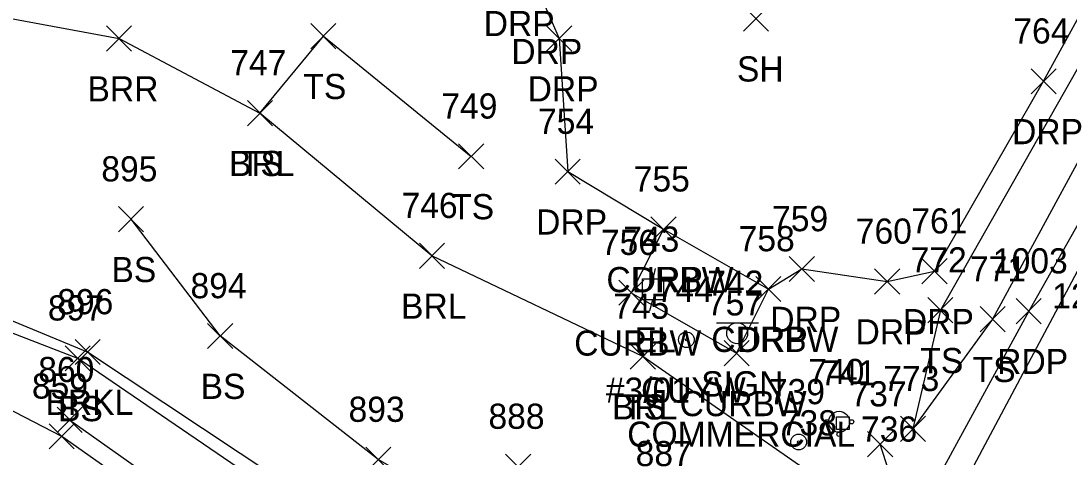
# Model space of a CAD drawing. Extents: x 1639430 to 1640195, y 612006 to 612917.
# Drawn here: x 1639766.2 to 1639849.6, y 612632.9 to 612667.5 of the extents above; entities that cross this region are included whole.
import ezdxf

# ---------------------------------------------------------------- set-up
doc = ezdxf.new("R2010")
doc.units = 0
for name, color, linetype in [('C_I', 7, 'Continuous'), ('CPBM', 7, 'Continuous'), ('D_I', 7, 'Continuous'), ('L_A', 7, 'Continuous'), ('L_I', 7, 'Continuous'), ('L_TIC', 7, 'Continuous'), ('LABL', 7, 'Continuous'), ('LAWE', 7, 'Continuous'), ('LELB', 7, 'Continuous'), ('M_I', 7, 'Continuous'), ('MPIR', 7, 'Continuous'), ('P_A', 7, 'Continuous'), ('P_I', 7, 'Continuous'), ('P_TIC', 7, 'Continuous'), ('PET', 7, 'Continuous'), ('R_A', 7, 'Continuous'), ('R_I', 7, 'Continuous'), ('R_TIC', 7, 'Continuous'), ('RC', 7, 'Continuous'), ('RDP', 7, 'Continuous'), ('RGR', 7, 'Continuous'), ('S_A', 7, 'Continuous'), ('S_C', 7, 'Continuous'), ('S_I', 7, 'Continuous'), ('SSGN', 7, 'Continuous'), ('U_A', 7, 'Continuous'), ('U_C', 7, 'Continuous'), ('U_I', 7, 'Continuous'), ('UEPT', 7, 'Continuous'), ('UPGW', 7, 'Continuous'), ('UW', 7, 'Continuous'), ('UWFH', 7, 'Continuous')]:
    doc.layers.add(name, color=color, linetype=linetype)

msp = doc.modelspace()

# ---------------------------------------------------------------- linework, layer by layer
at = {"layer": 'CPBM'}
for p, q in [((1639831.084, 612635.092), (1639831.084, 612636.092)), ((1639831.084, 612636.092), (1639832.084, 612636.092)), ((1639831.587, 612635.592), (1639831.587, 612635.592)), ((1639831.587, 612635.592), (1639831.587, 612635.592)), ((1639832.084, 612636.092), (1639832.084, 612635.092)), ((1639832.084, 612635.092), (1639831.084, 612635.092))]:
    msp.add_line(p, q, dxfattribs=at)
at = {"layer": 'L_TIC'}
for points in [[(1639823.679, 612666.738), (1639825.679, 612668.738)], [(1639825.679, 612666.738), (1639823.679, 612668.738)], [(1639773.027, 612665.155), (1639775.027, 612667.155)], [(1639775.027, 612665.155), (1639773.027, 612667.155)], [(1639789.272, 612665.346), (1639791.272, 612667.346)], [(1639791.272, 612665.346), (1639789.272, 612667.346)], [(1639784.228, 612659.23), (1639786.228, 612661.23)], [(1639786.228, 612659.23), (1639784.228, 612661.23)], [(1639784.228, 612659.23), (1639786.228, 612661.23)], [(1639786.228, 612659.23), (1639784.228, 612661.23)], [(1639801.028, 612655.794), (1639803.028, 612657.794)], [(1639803.028, 612655.794), (1639801.028, 612657.794)], [(1639773.976, 612650.801), (1639775.976, 612652.801)], [(1639775.976, 612650.801), (1639773.976, 612652.801)], [(1639797.909, 612647.895), (1639799.909, 612649.895)], [(1639799.909, 612647.895), (1639797.909, 612649.895)], [(1639838.342, 612643.566), (1639840.342, 612645.566)], [(1639840.342, 612643.566), (1639838.342, 612645.566)], [(1639842.497, 612642.862), (1639844.497, 612644.862)], [(1639844.497, 612642.862), (1639842.497, 612644.862)], [(1639781.07, 612641.52), (1639783.07, 612643.52)], [(1639783.07, 612641.52), (1639781.07, 612643.52)], [(1639770.525, 612640.248), (1639772.525, 612642.248)], [(1639772.525, 612640.248), (1639770.525, 612642.248)], [(1639769.728, 612639.749), (1639771.728, 612641.749)], [(1639771.728, 612639.749), (1639769.728, 612641.749)], [(1639814.683, 612639.888), (1639816.683, 612641.888)], [(1639816.683, 612639.888), (1639814.683, 612641.888)], [(1639814.683, 612639.888), (1639816.683, 612641.888)], [(1639816.683, 612639.888), (1639814.683, 612641.888)], [(1639769.094, 612634.855), (1639771.094, 612636.855)], [(1639771.094, 612634.855), (1639769.094, 612636.855)], [(1639768.465, 612633.546), (1639770.465, 612635.546)], [(1639770.465, 612633.546), (1639768.465, 612635.546)], [(1639836.164, 612634.143), (1639838.164, 612636.143)], [(1639838.164, 612634.143), (1639836.164, 612636.143)], [(1639836.164, 612634.143), (1639838.164, 612636.143)], [(1639838.164, 612634.143), (1639836.164, 612636.143)], [(1639793.64, 612631.699), (1639795.64, 612633.699)], [(1639795.64, 612631.699), (1639793.64, 612633.699)], [(1639804.765, 612631.144), (1639806.765, 612633.144)], [(1639806.765, 612631.144), (1639804.765, 612633.144)]]:
    msp.add_lwpolyline(points, dxfattribs=at)
at = {"layer": 'LABL'}
for points in [[(1639710.204, 612699.828), (1639711.051, 612687.806), (1639724.433, 612679.592), (1639743.791, 612671.782), (1639774.027, 612666.155)], [(1639774.027, 612666.155), (1639785.228, 612660.23)], [(1639815.683, 612640.888), (1639798.909, 612648.895), (1639785.228, 612660.23)]]:
    msp.add_lwpolyline(points, dxfattribs=at)
at = {"layer": 'LAWE'}
for points in [[(1639771.525, 612641.248), (1639744.188, 612652.549)], [(1639818.397, 612622.252), (1639806.958, 612625.66), (1639792.808, 612627.122), (1639771.525, 612641.248)], [(1639769.465, 612634.546), (1639758.328, 612640.278)], [(1639815.502, 612605.955), (1639811.555, 612610.222), (1639810.816, 612611.799), (1639809.099, 612612.433), (1639807.886, 612612.157), (1639806.874, 612611.255), (1639802.154, 612613.218), (1639796.025, 612614.881), (1639785.071, 612623.534), (1639769.465, 612634.546)]]:
    msp.add_lwpolyline(points, dxfattribs=at)
at = {"layer": 'LELB'}
for points in [[(1639856.893, 612675.516), (1639839.342, 612644.566), (1639837.164, 612635.143)], [(1639856.893, 612675.516), (1639858.232, 612671.011), (1639843.497, 612643.862), (1639837.164, 612635.143)], [(1639785.228, 612660.23), (1639790.272, 612666.346), (1639802.028, 612656.794)], [(1639806.958, 612625.66), (1639794.64, 612632.699), (1639782.07, 612642.52), (1639774.976, 612651.801)], [(1639745.954, 612650.314), (1639770.728, 612640.749)], [(1639764.188, 612527.424), (1639772.977, 612544.039), (1639792.096, 612560.955), (1639798.045, 612571.861), (1639798.637, 612584.242), (1639801.408, 612590.442), (1639806.01, 612591.217), (1639813.347, 612604.755), (1639814.159, 612604.989), (1639815.502, 612605.955), (1639817.508, 612607.626), (1639823.926, 612612.002), (1639825.414, 612614.447), (1639825.954, 612618.423), (1639826.214, 612622.256), (1639826.372, 612626.105), (1639824.294, 612621.683), (1639822.313, 612620.482), (1639821.077, 612619.388), (1639821.02, 612619.326), (1639817.573, 612621.321), (1639806.603, 612624.212), (1639792.365, 612626.015), (1639770.728, 612640.749)], [(1639770.341, 612524.498), (1639771.372, 612528.696), (1639778.638, 612537.492), (1639795.972, 612561.5), (1639808.106, 612583.963), (1639817.63, 612601.539), (1639820.453, 612607.731), (1639824.84, 612610.698), (1639833.386, 612626.603), (1639829.018, 612631.624), (1639815.683, 612640.888)], [(1639770.094, 612635.855), (1639784.877, 612625.393), (1639800.41, 612616.513), (1639807.846, 612612.518), (1639809.601, 612612.895), (1639810.878, 612612.379), (1639816.171, 612610.009), (1639817.508, 612607.626)]]:
    msp.add_lwpolyline(points, dxfattribs=at)
at = {"layer": 'MPIR'}
for radius in [0.625, 0.0833]:
    msp.add_circle((1639828.073, 612634.1), radius, dxfattribs=at)
at = {"layer": 'P_TIC'}
for points in [[(1639845.373, 612643.492), (1639847.373, 612645.492)], [(1639847.373, 612643.492), (1639845.373, 612645.492)]]:
    msp.add_lwpolyline(points, dxfattribs=at)
at = {"layer": 'PET'}
msp.add_lwpolyline([(1639860.191, 612668.905), (1639846.373, 612644.492), (1639830.054, 612614.558), (1639810.07, 612579.968), (1639792.174, 612548.775), (1639765.869, 612504.142)], dxfattribs=at)
at = {"layer": 'R_TIC'}
for points in [[(1639808.029, 612665.156), (1639810.029, 612667.156)], [(1639810.029, 612665.156), (1639808.029, 612667.156)], [(1639846.556, 612661.758), (1639848.556, 612663.758)], [(1639848.556, 612661.758), (1639846.556, 612663.758)], [(1639808.707, 612654.578), (1639810.707, 612656.578)], [(1639810.707, 612654.578), (1639808.707, 612656.578)], [(1639816.319, 612650), (1639818.319, 612652)], [(1639818.319, 612650), (1639816.319, 612652)], [(1639816.319, 612650), (1639818.319, 612652)], [(1639818.319, 612650), (1639816.319, 612652)], [(1639816.319, 612650), (1639818.319, 612652)], [(1639818.319, 612650), (1639816.319, 612652)], [(1639827.328, 612646.843), (1639829.328, 612648.843)], [(1639829.328, 612646.843), (1639827.328, 612648.843)], [(1639837.877, 612646.667), (1639839.877, 612648.667)], [(1639839.877, 612646.667), (1639837.877, 612648.667)], [(1639824.663, 612645.251), (1639826.663, 612647.251)], [(1639826.663, 612645.251), (1639824.663, 612647.251)], [(1639824.663, 612645.251), (1639826.663, 612647.251)], [(1639826.663, 612645.251), (1639824.663, 612647.251)], [(1639824.663, 612645.251), (1639826.663, 612647.251)], [(1639826.663, 612645.251), (1639824.663, 612647.251)], [(1639834.112, 612645.854), (1639836.112, 612647.854)], [(1639836.112, 612645.854), (1639834.112, 612647.854)], [(1639813.761, 612644.959), (1639815.761, 612646.959)], [(1639815.761, 612644.959), (1639813.761, 612646.959)], [(1639822.143, 612640.15), (1639824.143, 612642.15)], [(1639824.143, 612640.15), (1639822.143, 612642.15)], [(1639833.558, 612632.924), (1639835.558, 612634.924)], [(1639835.558, 612632.924), (1639833.558, 612634.924)]]:
    msp.add_lwpolyline(points, dxfattribs=at)
at = {"layer": 'RC'}
for points in [[(1639817.319, 612651), (1639814.761, 612645.959), (1639823.143, 612641.15), (1639825.663, 612646.251)], [(1639817.319, 612651), (1639825.663, 612646.251)]]:
    msp.add_lwpolyline(points, dxfattribs=at)
at = {"layer": 'RDP'}
for points in [[(1639825.663, 612646.251), (1639828.328, 612647.843), (1639835.112, 612646.854), (1639838.877, 612647.667), (1639847.556, 612662.758), (1639854.91, 612676.187), (1639857.768, 612677.278), (1639859.649, 612674.843), (1639860.03, 612669.42)], [(1639799.231, 612674.854), (1639805.536, 612671.346), (1639807.732, 612669.12), (1639809.029, 612666.156), (1639809.707, 612655.578), (1639817.319, 612651)]]:
    msp.add_lwpolyline(points, dxfattribs=at)
at = {"layer": 'RGR'}
msp.add_lwpolyline([(1639772.14, 612526.14), (1639776.867, 612528.109), (1639781.268, 612531.368), (1639783.057, 612534.432), (1639798.266, 612560.45), (1639810.049, 612582.033), (1639821.543, 612600.823), (1639833.331, 612621.737), (1639835.154, 612627.147), (1639835.455, 612631.126), (1639834.558, 612633.924)], dxfattribs=at)
at = {"layer": 'SSGN'}
for p, q in [((1639821.537, 612643.572), (1639824.87, 612643.572)), ((1639823.183, 612642.739), (1639823.183, 612642.739))]:
    msp.add_line(p, q, dxfattribs=at)
msp.add_circle((1639823.183, 612642.739), 0.833, dxfattribs=at)
at = {"layer": 'UEPT'}
for p, q in [((1639816.651, 612647.885), (1639816.485, 612647.052)), ((1639815.651, 612645.385), (1639815.651, 612647.052)), ((1639815.651, 612647.052), (1639817.318, 612647.052)), ((1639817.318, 612647.052), (1639817.318, 612645.385)), ((1639816.485, 612646.219), (1639816.485, 612646.219)), ((1639817.318, 612645.385), (1639815.651, 612645.385)), ((1639816.235, 612644.552), (1639816.485, 612645.385))]:
    msp.add_line(p, q, dxfattribs=at)
at = {"layer": 'UPGW'}
for radius in [0.625, 0.0833]:
    msp.add_circle((1639819.147, 612642.224), radius, dxfattribs=at)
at = {"layer": 'UW'}
msp.add_lwpolyline([(1639878.262, 612694.255), (1639853.445, 612653.711), (1639817.159, 612585.632)], dxfattribs=at)
at = {"layer": 'UWFH'}
msp.add_line((1639831.29, 612635.704), (1639831.29, 612635.704), dxfattribs=at)
for centre, radius in [((1639831.29, 612635.704), 0.833), ((1639830.29, 612635.704), 0.167), ((1639832.29, 612635.704), 0.167), ((1639831.29, 612634.704), 0.167)]:
    msp.add_circle(centre, radius, dxfattribs=at)

# ---------------------------------------------------------------- texts
at = {"layer": 'C_I'}
msp.add_text('741', height=2, dxfattribs=at).set_placement((1639829.792, 612638.592))
at = {"layer": 'D_I'}
msp.add_text('887', height=2, dxfattribs=at).set_placement((1639815.11, 612632.179))
at = {"layer": 'L_A'}
for s, p in [('SH', (1639823.167, 612662.738)), ('BRR', (1639771.515, 612661.155)), ('TS', (1639788.681, 612661.346)), ('BRL', (1639782.771, 612655.23)), ('TS', (1639783.637, 612655.23)), ('TS', (1639800.437, 612651.794)), ('BS', (1639773.417, 612646.801)), ('BRL', (1639796.452, 612643.895)), ('TS', (1639837.752, 612639.566)), ('TS', (1639841.907, 612638.862)), ('BS', (1639780.511, 612637.52)), ('BRKL', (1639768.171, 612636.248)), ('BRL', (1639813.227, 612635.888)), ('TS', (1639814.093, 612635.888)), ('BS', (1639769.169, 612635.749))]:
    msp.add_text(s, height=2, dxfattribs=at).set_placement(p)
at = {"layer": 'L_I'}
for s, p in [('747', (1639782.866, 612663.23)), ('747', (1639782.866, 612663.23)), ('749', (1639799.657, 612659.794)), ('895', (1639772.614, 612654.801)), ('746', (1639796.491, 612651.895)), ('772', (1639836.98, 612647.566)), ('771', (1639841.702, 612646.862)), ('894', (1639779.708, 612645.52)), ('896', (1639769.108, 612644.248)), ('897', (1639768.366, 612643.749)), ('745', (1639813.321, 612643.888)), ('745', (1639813.321, 612643.888)), ('860', (1639767.598, 612638.855)), ('859', (1639767.095, 612637.546)), ('773', (1639834.802, 612638.143)), ('773', (1639834.802, 612638.143)), ('893', (1639792.278, 612635.699)), ('888', (1639803.403, 612635.144)), ('738', (1639826.656, 612634.624))]:
    msp.add_text(s, height=2, dxfattribs=at).set_placement(p)
at = {"layer": 'M_I'}
msp.add_text('739', height=2, dxfattribs=at).set_placement((1639825.703, 612637.1))
at = {"layer": 'P_A'}
msp.add_text('RDP', height=2, dxfattribs=at).set_placement((1639843.861, 612639.492))
at = {"layer": 'P_I'}
msp.add_text('1003', height=2, dxfattribs=at).set_placement((1639843.523, 612647.492))
at = {"layer": 'R_A'}
for s, p in [('DRP', (1639803.025, 612666.346)), ('DRP', (1639805.22, 612664.12)), ('DRP', (1639806.518, 612661.156)), ('DRP', (1639845.044, 612657.758)), ('DRP', (1639807.195, 612650.578)), ('CURBW', (1639812.784, 612646)), ('CURBW', (1639812.784, 612646)), ('DRP', (1639814.807, 612646)), ('DRP', (1639825.816, 612642.843)), ('DRP', (1639836.365, 612642.667)), ('DRP', (1639832.6, 612641.854)), ('CURBW', (1639810.225, 612640.959)), ('CURBW', (1639821.127, 612641.251)), ('CURBW', (1639821.127, 612641.251)), ('DRP', (1639823.151, 612641.251)), ('CURBW', (1639818.608, 612636.15))]:
    msp.add_text(s, height=2, dxfattribs=at).set_placement(p)
at = {"layer": 'R_I'}
for s, p in [('764', (1639845.147, 612665.758)), ('754', (1639807.344, 612658.578)), ('755', (1639814.957, 612654)), ('755', (1639814.957, 612654)), ('755', (1639814.957, 612654)), ('759', (1639825.958, 612650.843)), ('761', (1639837.034, 612650.667)), ('758', (1639823.301, 612649.251)), ('758', (1639823.301, 612649.251)), ('758', (1639823.301, 612649.251)), ('760', (1639832.616, 612649.854)), ('756', (1639812.343, 612648.959)), ('757', (1639820.781, 612644.15)), ('737', (1639832.196, 612636.924)), ('736', (1639833.038, 612634.126))]:
    msp.add_text(s, height=2, dxfattribs=at).set_placement(p)
at = {"layer": 'S_A'}
msp.add_text('SIGN', height=2, dxfattribs=at).set_placement((1639820.321, 612637.718))
at = {"layer": 'S_C'}
msp.add_text('COMMERCIAL', height=2, dxfattribs=at).set_placement((1639814.439, 612633.718))
at = {"layer": 'S_I'}
msp.add_text('742', height=2, dxfattribs=at).set_placement((1639820.802, 612645.718))
at = {"layer": 'U_A'}
for s, p in [('EL', (1639815.02, 612641.219)), ('GUYW', (1639815.541, 612637.224))]:
    msp.add_text(s, height=2, dxfattribs=at).set_placement(p)
at = {"layer": 'U_C'}
for s, p in [('12" MAIN', (1639848.24, 612644.711)), ('#3/01', (1639812.737, 612637.219))]:
    msp.add_text(s, height=2, dxfattribs=at).set_placement(p)
at = {"layer": 'U_I'}
for s, p in [('743', (1639814.123, 612649.219)), ('744', (1639816.785, 612645.224)), ('740', (1639828.841, 612638.704))]:
    msp.add_text(s, height=2, dxfattribs=at).set_placement(p)

doc.saveas('drawing.dxf')
